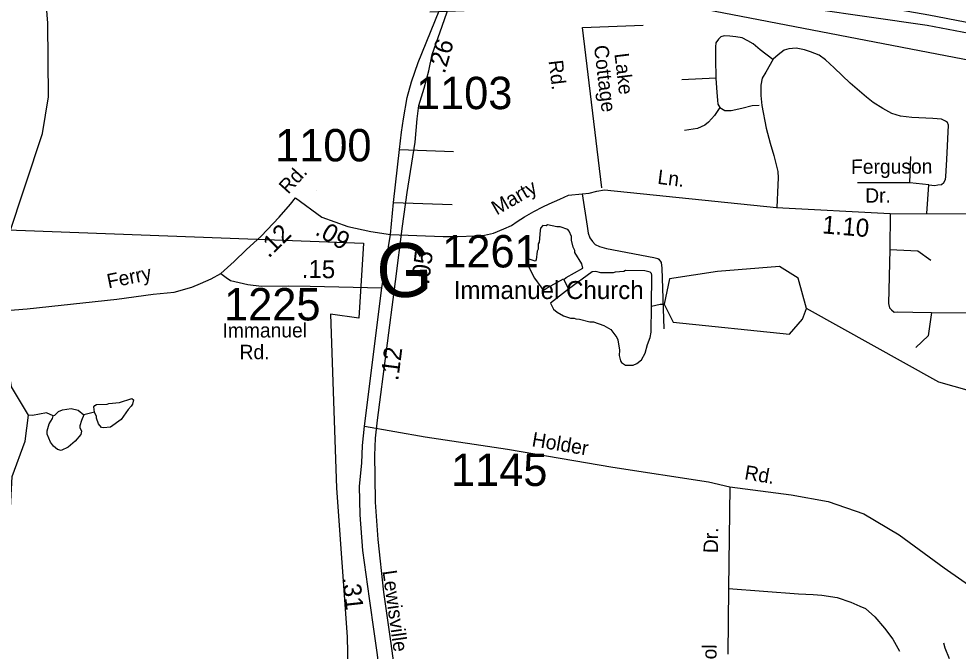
# Model space of a CAD drawing. Extents: x 1551653 to 1702041, y 811336 to 920032.
# Drawn here: x 1587539 to 1591821, y 846549 to 849433 of the extents above; entities that cross this region are included whole.
import ezdxf

# ---------------------------------------------------------------- set-up
doc = ezdxf.new("R2010")
doc.units = 0
for name, color, linetype in [('Old_Level_10', 7, 'Continuous'), ('Old_Level_11', 7, 'Continuous'), ('Old_Level_17', 7, 'Continuous'), ('Old_Level_22', 7, 'Continuous'), ('Old_Level_28', 7, 'Continuous'), ('Old_Level_3', 7, 'Continuous'), ('Old_Level_32', 7, 'Continuous'), ('Old_Level_35', 7, 'Continuous'), ('Old_Level_48', 7, 'Continuous'), ('Old_Level_49', 7, 'Continuous'), ('Old_Level_59', 7, 'Continuous'), ('Old_Level_60', 7, 'Continuous'), ('Old_Level_62', 7, 'Continuous'), ('Old_Level_8', 7, 'Continuous')]:
    doc.layers.add(name, color=color, linetype=linetype)

msp = doc.modelspace()

# ---------------------------------------------------------------- linework, layer by layer
at = {"layer": 'Old_Level_28'}
for points in [[(1596506.718, 848509.832), (1596372.895, 848533.982), (1596223.714, 848560.328), (1595962.266, 848607.753), (1595714.667, 848662.132), (1595389.26, 848736.877), (1595059.232, 848790.937), (1594838.535, 848830.893), (1594539.451, 848885.908), (1594246.735, 848937.269), (1593923.597, 848997.937), (1593737.116, 849033.994), (1592992.496, 849174.633), (1592262.746, 849338.758), (1591688.024, 849449.061), (1590927.32, 849582.734), (1590621.544, 849639.267)], [(1590453.291, 849599.748), (1590596.984, 849570.445), (1590897.847, 849516.37), (1591679.613, 849404.74), (1592254.285, 849294.447), (1593119.738, 849084.615), (1593823.957, 848941.906), (1594286.855, 848867.258), (1594656.189, 848811.042), (1595128.102, 848723.103), (1595435.676, 848659.351), (1595944.644, 848547.378), (1596389.991, 848470.535), (1596495.295, 848448.579)]]:
    msp.add_lwpolyline(points, dxfattribs=at)
at = {"layer": 'Old_Level_3'}
for p, q in [((1589310.123, 848641.222), (1589345.392, 848870.88)), ((1589287.978, 848487.843), (1589310.123, 848641.222)), ((1589255.989, 848234.398), (1589287.978, 848487.843)), ((1589174.789, 847602.838), (1589255.989, 848234.398))]:
    msp.add_line(p, q, dxfattribs=at)
for points in [[(1589423.312, 849270.321), (1589469.244, 849399.914), (1589512.715, 849527.047)], [(1589345.392, 848870.88), (1589355.235, 848976.687), (1589363.437, 849037.382), (1589387.223, 849116.942), (1589408.548, 849196.503), (1589423.312, 849270.321)], [(1589310.123, 845996.05), (1589287.157, 846215.045), (1589236.304, 846584.139), (1589203.496, 846818.719), (1589177.249, 847059.04), (1589165.767, 847228.823), (1589163.306, 847345.292), (1589162.486, 847441.257), (1589165.767, 847520.817), (1589174.789, 847602.838)]]:
    msp.add_lwpolyline(points, dxfattribs=at)
at = {"layer": 'Old_Level_32'}
for p, q in [((1589193.405, 848206.542), (1589234.383, 848450.052)), ((1589115.511, 847575.755), (1589193.405, 848206.542))]:
    msp.add_line(p, q, dxfattribs=at)
for points in [[(1589234.383, 848450.052), (1589246.923, 848594.714), (1589274.935, 848836.324), (1589283.434, 848916.274), (1589293.631, 848977.513), (1589308.927, 849074.473), (1589329.323, 849145.918), (1589359.916, 849234.372), (1589416.72, 849372.463), (1589459.222, 849477.119), (1589482.072, 849526.373)], [(1589234.383, 848450.052), (1589473.968, 848440.471), (1589539.969, 848439.568), (1589618.619, 848443.548), (1589662.72, 848446.849), (1589703.548, 848455.363), (1589750.431, 848474.471), (1589784.729, 848489.773), (1589810.512, 848508.754), (1589845.013, 848530.253), (1589887.579, 848553.811), (1589928.27, 848576.143), (1589957.015, 848589.869), (1590005.123, 848610.234), (1590044.686, 848628.179), (1590106.846, 848635.09), (1590139.086, 848637.915), (1590174.184, 848647.188), (1590208.717, 848652.372), (1590993.589, 848572.581), (1591510.681, 848545.755), (1591889.91, 848543.356)], [(1588460.615, 848270.794), (1588521.048, 848326.095), (1588576.299, 848379.668), (1588643.638, 848441.881), (1588726.517, 848528.289), (1588778.111, 848588.321), (1588800.518, 848616.081), (1588920.785, 848527.808), (1589038.793, 848486.47), (1589144.118, 848462.276), (1589234.383, 848450.052)], [(1586262.994, 848189.644), (1586339.604, 848118.56), (1586381.363, 848082.877), (1586419.637, 848051.809), (1586465.328, 848033.705), (1586519.029, 848021.005), (1586608.598, 848012.337), (1586764.962, 848025.109), (1587328.077, 848090.237), (1587577.067, 848111.004), (1587986.467, 848154.006), (1588152.673, 848176.726), (1588248.239, 848186.115), (1588327.665, 848208.581), (1588367.377, 848225.862), (1588415.723, 848246.6), (1588460.615, 848270.794)], [(1588460.615, 848270.794), (1588484.788, 848253.513), (1588505.13, 848239.796), (1588543.493, 848231.047), (1588583.022, 848220.672), (1588645.122, 848213.871), (1588769.024, 848214.603), (1588867.121, 848213.206), (1589193.405, 848206.542)], [(1589236.373, 845985.193), (1589220.031, 846178.726), (1589172.414, 846542.412), (1589160.46, 846628.44), (1589138.059, 846789.093), (1589107.311, 847008.617), (1589095.012, 847170.695), (1589092.962, 847301.999), (1589103.639, 847406.701), (1589106.739, 847486.701), (1589115.511, 847575.755)], [(1589115.511, 847575.755), (1589391.398, 847527.101), (1589766.271, 847470.565), (1590246.416, 847388.33), (1590682.912, 847321.515), (1590780.618, 847299.005), (1591060.352, 847262.409), (1591228.601, 847231.784), (1591390.361, 847175.248), (1591552.121, 847080.164), (1591757.531, 846928.545), (1591918.676, 846816.301), (1592011.11, 846749.486), (1592080.436, 846667.251), (1592231.926, 846459.096)]]:
    msp.add_lwpolyline(points, dxfattribs=at)
at = {"layer": 'Old_Level_35'}
for p, q in [((1590109.074, 849393.106), (1590385.019, 849403.8)), ((1590196.121, 848662.204), (1590109.074, 849393.106)), ((1590716.543, 849162.25), (1590561.913, 849155.424)), ((1589274.935, 848836.324), (1589520.322, 848828.004)), ((1591601.116, 848684.428), (1591605.663, 848805.02)), ((1591601.116, 848684.428), (1591362.349, 848684.428)), ((1591687.527, 848675.326), (1591601.116, 848684.428)), ((1591678.365, 848544.694), (1591687.527, 848675.326)), ((1589246.923, 848594.714), (1589514.316, 848586.605)), ((1591510.681, 848545.755), (1591509.113, 848381.125)), ((1591698.715, 848094.199), (1591862.621, 848091.927)), ((1590780.618, 847299.005), (1590774.02, 846834.908)), ((1590774.02, 846834.908), (1590771.619, 846534.708))]:
    msp.add_line(p, q, dxfattribs=at)
for points in [[(1590976.227, 849247.073), (1590918.926, 849291.944), (1590887.09, 849319.248), (1590862.076, 849332.901), (1590837.063, 849346.553), (1590807.501, 849351.104), (1590780.214, 849353.379), (1590755.2, 849355.654), (1590739.283, 849351.104), (1590727.912, 849339.727), (1590716.543, 849323.8), (1590714.269, 849305.597), (1590714.269, 849250.988), (1590716.543, 849162.25)], [(1591687.527, 848675.326), (1591714.814, 848673.051), (1591728.457, 848675.326), (1591744.375, 848677.602), (1591755.745, 848686.703), (1591762.567, 848700.355), (1591764.841, 848714.007), (1591769.389, 848791.369), (1591776.211, 848948.367), (1591771.663, 848959.745), (1591762.567, 848966.57), (1591744.375, 848975.671), (1591705.718, 848977.947), (1591610.211, 848982.498), (1591557.91, 848989.324), (1591519.253, 849000.701), (1591478.322, 849023.454), (1591432.842, 849050.758), (1591403.281, 849075.787), (1591328.24, 849139.496), (1591255.473, 849210.032), (1591216.816, 849246.438), (1591187.254, 849266.916), (1591148.596, 849282.843), (1591121.309, 849291.944), (1591082.652, 849298.77), (1591048.542, 849296.495), (1591028.076, 849289.669), (1591000.788, 849269.191), (1590978.049, 849248.713)], [(1590978.049, 849248.713), (1590943.94, 849189.554), (1590928.022, 849162.25), (1590921.199, 849130.395), (1590921.199, 849082.613), (1590925.747, 849037.106)], [(1590716.543, 849162.25), (1590721.091, 849096.265), (1590723.365, 849062.134), (1590725.639, 849043.932), (1590734.735, 849028.005)], [(1590734.735, 849028.005), (1590709.721, 848991.599), (1590682.433, 848962.02), (1590666.516, 848948.367), (1590632.406, 848932.44), (1590573.283, 848923.339)], [(1590734.735, 849028.005), (1590757.474, 849014.352), (1590787.035, 849014.352), (1590834.789, 849025.729), (1590882.542, 849037.106), (1590914.378, 849039.381)], [(1590925.747, 849037.106), (1590946.213, 848934.716), (1590964.406, 848866.455), (1590980.323, 848809.572), (1590991.693, 848766.34), (1590998.515, 848736.76), (1591000.788, 848707.181), (1590998.515, 848675.326), (1590994.049, 848572.529)], [(1590106.846, 848635.09), (1590129.52, 848487.004), (1590135.121, 848454.905), (1590142.919, 848434.705), (1590154.52, 848416.703), (1590166.522, 848404.403), (1590186.321, 848394.003), (1590218.119, 848385.604), (1590433.621, 848344.603), (1590451.521, 848340.203), (1590457.42, 848336.102), (1590467.42, 848322.103), (1590470.819, 848296.004), (1590479.119, 848019.705)], [(1591509.113, 848381.125), (1591502.845, 848134.964), (1591507.547, 848114.581), (1591516.948, 848105.174), (1591529.484, 848095.767), (1591545.153, 848097.335), (1591614.099, 848095.767), (1591698.715, 848094.199)], [(1591509.113, 848381.125), (1591637.604, 848374.854), (1591697.148, 848332.521)], [(1591698.715, 848094.199), (1591684.612, 847987.581), (1591628.202, 847934.272)], [(1590774.02, 846834.908), (1591093.718, 846810.206), (1591159.718, 846807.208), (1591199.718, 846804.806), (1591269.718, 846793.806), (1591331.319, 846772.707), (1591373.117, 846754.308), (1591398.917, 846743.806), (1591440.417, 846705.308), (1591485.617, 846654.508), (1591523.018, 846604.006), (1591554.117, 846549.508)]]:
    msp.add_lwpolyline(points, dxfattribs=at)
at = {"layer": 'Old_Level_48'}
for points in [[(1586285.343, 850744.647), (1586149.012, 849368.848), (1586194.014, 849301.284), (1586149.012, 848520.544), (1589110.183, 848410.134), (1589089.466, 848068.285), (1588960.336, 848086.743), (1588988.006, 847293.019), (1589035.598, 846614.073)], [(1596197.421, 846117.581), (1596338.524, 847290.486), (1596904.927, 847270.334), (1596283.958, 847806.568), (1595748.221, 848233.118), (1595309.89, 848452.486), (1594414.385, 848690.85), (1593223.582, 848983.51), (1590507.715, 849506.118), (1589412.775, 849462.647)], [(1589035.598, 846614.073), (1589058.099, 845600.612)]]:
    msp.add_lwpolyline(points, dxfattribs=at)
at = {"layer": 'Old_Level_49'}
for points in [[(1586285.343, 850744.647), (1586149.012, 849368.848), (1586194.014, 849301.284), (1586149.012, 848520.544), (1589110.183, 848410.134), (1589089.466, 848068.285), (1588960.336, 848086.743), (1588988.006, 847293.019), (1589035.598, 846614.073)], [(1596197.421, 846117.581), (1596338.524, 847290.486), (1596904.927, 847270.334), (1596283.958, 847806.568), (1595748.221, 848233.118), (1595309.89, 848452.486), (1594414.385, 848690.85), (1593223.582, 848983.51), (1590507.715, 849506.118), (1589412.775, 849462.647)], [(1589035.598, 846614.073), (1589058.099, 845600.612)]]:
    msp.add_lwpolyline(points, dxfattribs=at)
at = {"layer": 'Old_Level_59'}
for points in [[(1587450.586, 846262.252), (1587508.557, 847345.054), (1587568.815, 847506.465), (1587584.28, 847624.925), (1587505.54, 847754.826), (1587475.193, 847949.318), (1587490.571, 848437.906), (1587647.539, 848910.704), (1587675.528, 849077.617), (1587671.53, 849412.467), (1587660.56, 849546.571), (1587568.594, 849795.351), (1587582.537, 850146.4), (1587755.601, 850586.031), (1587750.577, 850835.58), (1587582.537, 851321.553)], [(1593705.803, 847052.83), (1593390.031, 847269.603), (1593203.63, 847445.607), (1593089.802, 847577.456), (1592981.842, 847612.417), (1592399.108, 847637.177), (1592131.344, 847663.072), (1591732.441, 847775.352), (1591129.631, 848111.411)]]:
    msp.add_lwpolyline(points, dxfattribs=at)
at = {"layer": 'Old_Level_60'}
msp.add_lwpolyline([(1591129.631, 848111.411), (1591091.34, 848249.762), (1591007.397, 848303.534), (1590724.228, 848281.13), (1590504.857, 848247.522), (1590481.408, 848130.917), (1590521.645, 848049.24), (1591052.531, 847994.737), (1591110.768, 848063.113), (1591129.631, 848111.411)], dxfattribs=at)
at = {"layer": 'Old_Level_62'}
for p, q in [((1590023.067, 848243.824), (1590044.495, 848199.635)), ((1587884.579, 847639.689), (1587835.982, 847626.873))]:
    msp.add_line(p, q, dxfattribs=at)
for points in [[(1590023.067, 848243.824), (1590034.755, 848252.487), (1590110.829, 848295.805), (1590105.498, 848315.592), (1590074.125, 848367.931), (1590074.228, 848375.928), (1590066.436, 848392.025), (1590058.746, 848424.116), (1590058.951, 848440.11), (1590047.263, 848464.255), (1590041.317, 848472.303), (1590007.483, 848484.709), (1589991.489, 848484.914), (1589949.659, 848493.475), (1589943.609, 848489.527), (1589927.615, 848489.732), (1589917.465, 848477.891), (1589915.312, 848467.894), (1589910.699, 848413.966), (1589906.598, 848406.02), (1589906.29, 848382.029), (1589902.189, 848374.083), (1589897.78, 848334.2), (1589893.679, 848328.254), (1589865.792, 848336.558), (1589854.822, 848332.612), (1589855.95, 848321.231), (1589861.384, 848306.672), (1589890.706, 848250.283), (1589918.286, 848209.99), (1589928.743, 848194.612), (1589948.223, 848205.582), (1590021.427, 848247.105), (1590023.067, 848243.824)], [(1590423.124, 848122.843), (1590424.764, 848263.56), (1590422.919, 848271.609), (1590416.972, 848277.658), (1590393.084, 848283.963), (1590305.116, 848285.09), (1590297.017, 848281.194), (1590257.032, 848277.708), (1590248.932, 848273.812), (1590192.953, 848274.479), (1590169.064, 848280.784), (1590153.07, 848278.99), (1590044.495, 848199.635)], [(1590044.495, 848199.635), (1589962.577, 848135.607), (1589977.033, 848109.258), (1589992.925, 848095.11), (1590022.657, 848078.705), (1590054.543, 848068.35), (1590070.537, 848068.145), (1590078.534, 848064.044), (1590094.528, 848063.839), (1590142.305, 848051.228), (1590158.299, 848051.023), (1590206.076, 848034.414), (1590237.859, 848016.062), (1590265.439, 847979.717), (1590269.335, 847969.669), (1590276.717, 847921.585), (1590276.512, 847897.594), (1590282.15, 847873.551), (1590286.149, 847865.503), (1590303.989, 847853.302), (1590339.975, 847852.841), (1590356.072, 847860.633), (1590378.217, 847878.319), (1590394.622, 847908.102), (1590405.079, 847947.985), (1590417.382, 847979.819), (1590421.688, 848003.759), (1590423.124, 848122.843)], [(1590423.124, 848122.843), (1590463.211, 848131.148), (1590481.408, 848130.917)], [(1587884.579, 847639.689), (1587882.221, 847663.834), (1587886.322, 847669.781), (1587894.319, 847673.677), (1587942.301, 847675.06), (1587950.401, 847678.956), (1587998.383, 847682.391), (1588054.67, 847701.666), (1588062.564, 847695.566), (1588058.361, 847675.625), (1588052.209, 847665.68), (1588038.06, 847651.89), (1588005.457, 847606.317), (1587957.065, 847570.946), (1587925.077, 847567.357), (1587917.08, 847569.459), (1587903.239, 847585.607), (1587893.601, 847611.699), (1587893.704, 847619.696), (1587884.579, 847639.689)], [(1587696.649, 847622.926), (1587703.826, 847626.105), (1587720.025, 847641.894), (1587738.069, 847649.634), (1587778.157, 847655.17), (1587810.043, 847648.763), (1587835.982, 847626.873)], [(1587696.649, 847622.926), (1587665.891, 847636.562), (1587601.812, 847623.387), (1587584.28, 847624.925)], [(1587835.982, 847626.873), (1587825.524, 847600.576), (1587817.219, 847576.687), (1587817.117, 847568.69), (1587824.909, 847552.593), (1587822.756, 847536.65), (1587796.407, 847506.969), (1587764.008, 847479.39), (1587731.918, 847463.806), (1587715.924, 847468.009), (1587698.084, 847484.259), (1587684.346, 847502.407), (1587668.762, 847538.598), (1587668.967, 847554.592), (1587677.374, 847586.427), (1587693.573, 847610.213), (1587696.649, 847622.926)], [(1591754.629, 846587.618), (1591760.371, 846563.525), (1591779.748, 846515.286)]]:
    msp.add_lwpolyline(points, dxfattribs=at)
at = {"layer": 'Old_Level_8'}
msp.add_line((1588894.24, 848650.662), (1588894.24, 848650.662), dxfattribs=at)

# ---------------------------------------------------------------- texts
at = {"layer": 'Old_Level_10'}
for s, rotation, p in [('Cottage', 276.791678, (1590160.622, 849309.253)), ('Rd.', 276.791678, (1589954.067, 849241.182)), ('Lake', 276.791678, (1590254.04, 849273.212)), ('Ferguson', 0.298667, (1591333.001, 848725.678)), ('Dr.', 0.294364, (1591397.526, 848594.461)), ('Dr.', 89.185519, (1590725.633, 846995.672)), ('School', 88.609233, (1590714.076, 846310.837))]:
    msp.add_text(s, height=65.6167, rotation=rotation, dxfattribs=at).set_placement(p)
at = {"layer": 'Old_Level_11'}
for s, rotation, p in [('Rd.', 47.687692, (1588766.854, 848630.427)), ('Ln.', 352.759289, (1590448.031, 848680.935)), ('Marty', 29.926875, (1589717.842, 848535.713)), ('Ferry', 11.500672, (1587948.259, 848203.137)), ('Immanuel', 0.140667, (1588467.986, 847979.115)), ('Rd.', 359.957114, (1588545.542, 847880.667)), ('Holder', 350.414139, (1589874.842, 847484.185)), ('Rd.', 350.414139, (1590843.867, 847333.511)), ('Lewisville', 277.911572, (1589197.085, 846914.432))]:
    msp.add_text(s, height=65.6167, rotation=rotation, dxfattribs=at).set_placement(p)
at = {"layer": 'Old_Level_17'}
for s, rotation, p in [('.26', 73.769053, (1589480.45, 849179.45)), ('1.10', 355.176328, (1591199.139, 848454.95)), ('.12', 44.796542, (1588679.138, 848338.829)), ('.09', 329.922331, (1588885.43, 848451.507)), ('.05', 82.916058, (1589408.674, 848218.177)), ('.15', 359.183733, (1588828.691, 848251.571)), ('.12', 82.659528, (1589268.367, 847779.791)), ('.31', 276.266375, (1589013.545, 846883.544))]:
    msp.add_text(s, height=82.0208, rotation=rotation, dxfattribs=at).set_placement(p)
at = {"layer": 'Old_Level_22'}
msp.add_text('G', height=246.062, rotation=0.658783, dxfattribs=at).set_placement((1589170.738, 848162.788))
msp.add_text('Immanuel Church', height=82.02083, dxfattribs=at).set_placement((1589521.76, 848155.063))
at = {"layer": 'Old_Level_8'}
for s, p in [('1103', (1589349.936, 849020.99)), ('1100', (1588707.925, 848782.793)), ('1261', (1589469.736, 848298.993)), ('1225', (1588475.318, 848057.4)), ('1145', (1589509.632, 847302.425))]:
    msp.add_text(s, height=147.6375, dxfattribs=at).set_placement(p)

doc.saveas('drawing.dxf')
